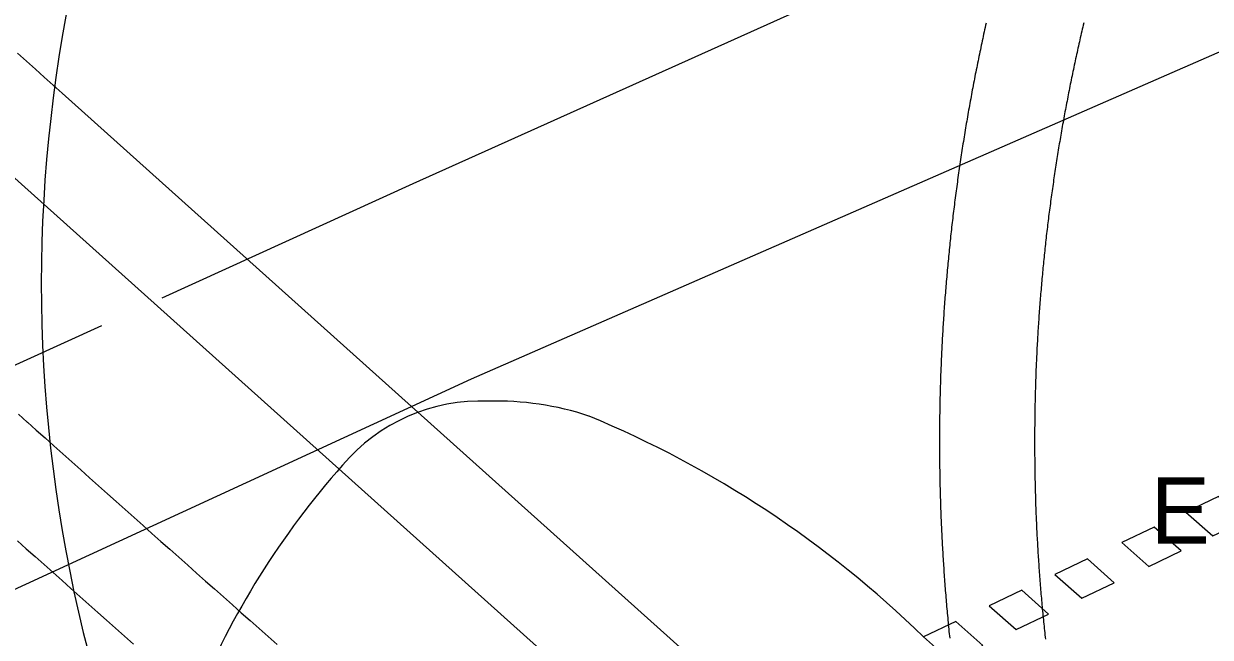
# Model space of a CAD drawing. Extents: x 81617 to 82144, y 454649 to 455150.
# Drawn here: x 81697.46 to 81715.37, y 454732.19 to 454741.45 of the extents above; entities that cross this region are included whole.
import ezdxf

# ---------------------------------------------------------------- set-up
doc = ezdxf.new("R2010")
doc.units = 0
doc.layers.add('B-WE-OG-TOPOGRAFIE-G', color=7, linetype='Continuous')
doc.layers.add('B-WE-VW-MARKERING-G', color=7, linetype='Continuous')

msp = doc.modelspace()

# ---------------------------------------------------------------- linework, layer by layer
at = {"layer": 'B-WE-OG-TOPOGRAFIE-G'}
for points in [[(81711.983, 454741.464), (81711.975, 454741.43), (81711.968, 454741.397), (81711.96, 454741.363), (81711.953, 454741.329), (81711.945, 454741.296), (81711.938, 454741.262), (81711.931, 454741.229), (81711.924, 454741.195), (81711.916, 454741.162), (81711.909, 454741.128), (81711.902, 454741.094), (81711.895, 454741.061), (81711.888, 454741.027), (81711.881, 454740.994), (81711.874, 454740.96), (81711.867, 454740.926), (81711.86, 454740.893), (81711.853, 454740.859), (81711.846, 454740.825), (81711.84, 454740.792), (81711.833, 454740.758), (81711.826, 454740.724), (81711.819, 454740.691), (81711.813, 454740.657), (81711.806, 454740.623), (81711.8, 454740.59), (81711.793, 454740.556), (81711.787, 454740.522), (81711.78, 454740.488), (81711.774, 454740.455), (81711.768, 454740.421), (81711.761, 454740.387), (81711.755, 454740.353), (81711.749, 454740.319), (81711.743, 454740.286), (81711.737, 454740.252), (81711.731, 454740.218), (81711.724, 454740.184), (81711.718, 454740.15), (81711.712, 454740.117), (81711.707, 454740.083), (81711.701, 454740.049), (81711.695, 454740.015), (81711.689, 454739.981), (81711.683, 454739.947), (81711.678, 454739.914), (81711.672, 454739.88), (81711.666, 454739.846), (81711.661, 454739.812), (81711.655, 454739.778), (81711.649, 454739.744), (81711.644, 454739.71), (81711.639, 454739.676), (81711.633, 454739.642), (81711.628, 454739.608), (81711.622, 454739.574), (81711.617, 454739.541), (81711.612, 454739.507), (81711.607, 454739.473), (81711.602, 454739.439), (81711.596, 454739.405), (81711.591, 454739.371), (81711.586, 454739.337), (81711.581, 454739.303), (81711.576, 454739.269), (81711.572, 454739.235), (81711.567, 454739.201), (81711.562, 454739.167), (81711.557, 454739.133), (81711.552, 454739.099), (81711.548, 454739.065), (81711.543, 454739.031), (81711.538, 454738.997), (81711.534, 454738.963), (81711.529, 454738.929), (81711.525, 454738.895), (81711.52, 454738.861), (81711.516, 454738.826), (81711.511, 454738.792), (81711.507, 454738.758), (81711.503, 454738.724), (81711.498, 454738.69), (81711.494, 454738.656), (81711.49, 454738.622), (81711.486, 454738.588), (81711.482, 454738.554), (81711.478, 454738.52), (81711.474, 454738.486), (81711.47, 454738.451), (81711.466, 454738.417), (81711.462, 454738.383), (81711.458, 454738.349), (81711.454, 454738.315), (81711.45, 454738.281), (81711.447, 454738.247), (81711.443, 454738.212), (81711.439, 454738.178), (81711.436, 454738.144), (81711.432, 454738.11), (81711.429, 454738.076), (81711.425, 454738.042), (81711.422, 454738.008), (81711.418, 454737.973), (81711.415, 454737.939), (81711.412, 454737.905), (81711.408, 454737.871), (81711.405, 454737.837), (81711.402, 454737.802), (81711.399, 454737.768), (81711.396, 454737.734), (81711.393, 454737.7), (81711.389, 454737.666), (81711.387, 454737.631), (81711.384, 454737.597), (81711.381, 454737.563), (81711.378, 454737.529), (81711.375, 454737.494), (81711.372, 454737.46), (81711.369, 454737.426), (81711.367, 454737.392), (81711.364, 454737.357), (81711.361, 454737.323), (81711.359, 454737.289), (81711.356, 454737.255), (81711.354, 454737.22), (81711.351, 454737.186), (81711.349, 454737.152), (81711.346, 454737.118), (81711.344, 454737.083), (81711.342, 454737.049), (81711.34, 454737.015), (81711.337, 454736.981), (81711.335, 454736.946), (81711.333, 454736.912), (81711.331, 454736.878), (81711.329, 454736.843), (81711.327, 454736.809), (81711.325, 454736.775), (81711.323, 454736.741), (81711.321, 454736.706), (81711.319, 454736.672), (81711.317, 454736.638), (81711.316, 454736.603), (81711.314, 454736.569), (81711.312, 454736.535), (81711.311, 454736.5), (81711.309, 454736.466), (81711.307, 454736.432), (81711.306, 454736.398), (81711.304, 454736.363), (81711.303, 454736.329), (81711.302, 454736.295), (81711.3, 454736.26), (81711.299, 454736.226), (81711.298, 454736.192), (81711.296, 454736.157), (81711.295, 454736.123), (81711.294, 454736.089), (81711.293, 454736.054), (81711.292, 454736.02), (81711.291, 454735.986), (81711.29, 454735.951), (81711.289, 454735.917), (81711.288, 454735.883), (81711.287, 454735.848), (81711.286, 454735.814), (81711.286, 454735.78), (81711.285, 454735.745), (81711.284, 454735.711), (81711.283, 454735.677), (81711.283, 454735.642), (81711.282, 454735.608), (81711.282, 454735.574), (81711.281, 454735.539), (81711.281, 454735.505), (81711.28, 454735.471), (81711.28, 454735.436), (81711.28, 454735.402), (81711.279, 454735.367), (81711.279, 454735.333), (81711.279, 454735.299), (81711.279, 454735.264), (81711.279, 454735.23), (81711.279, 454735.196), (81711.278, 454735.161), (81711.278, 454735.127), (81711.279, 454735.093), (81711.279, 454735.058), (81711.279, 454735.024), (81711.279, 454734.99), (81711.279, 454734.955), (81711.279, 454734.921), (81711.28, 454734.887), (81711.28, 454734.852), (81711.28, 454734.818), (81711.281, 454734.784), (81711.281, 454734.749), (81711.282, 454734.715), (81711.282, 454734.681), (81711.283, 454734.646), (81711.283, 454734.612), (81711.284, 454734.578), (81711.285, 454734.543), (81711.285, 454734.509), (81711.286, 454734.475), (81711.287, 454734.44), (81711.288, 454734.406), (81711.289, 454734.372), (81711.29, 454734.337), (81711.291, 454734.303), (81711.292, 454734.269), (81711.293, 454734.234), (81711.294, 454734.2), (81711.295, 454734.166), (81711.296, 454734.131), (81711.298, 454734.097), (81711.299, 454734.063), (81711.3, 454734.028), (81711.301, 454733.994), (81711.303, 454733.96), (81711.304, 454733.925), (81711.306, 454733.891), (81711.307, 454733.857), (81711.309, 454733.822), (81711.31, 454733.788), (81711.312, 454733.754), (81711.314, 454733.719), (81711.316, 454733.685), (81711.317, 454733.651), (81711.319, 454733.616), (81711.321, 454733.582), (81711.323, 454733.548), (81711.325, 454733.514), (81711.327, 454733.479), (81711.329, 454733.445), (81711.331, 454733.411), (81711.333, 454733.376), (81711.335, 454733.342), (81711.337, 454733.308), (81711.339, 454733.274), (81711.342, 454733.239), (81711.344, 454733.205), (81711.346, 454733.171), (81711.349, 454733.137), (81711.351, 454733.102), (81711.354, 454733.068), (81711.356, 454733.034), (81711.359, 454732.999), (81711.361, 454732.965), (81711.364, 454732.931), (81711.366, 454732.897), (81711.369, 454732.863), (81711.372, 454732.828), (81711.375, 454732.794), (81711.378, 454732.76), (81711.38, 454732.726), (81711.383, 454732.691), (81711.386, 454732.657), (81711.389, 454732.623), (81711.392, 454732.589), (81711.395, 454732.555), (81711.398, 454732.52), (81711.402, 454732.486), (81711.405, 454732.452), (81711.408, 454732.418), (81711.411, 454732.384), (81711.415, 454732.349), (81711.418, 454732.315), (81711.421, 454732.281), (81711.425, 454732.247), (81711.428, 454732.213), (81711.432, 454732.178)], [(81713.456, 454741.466), (81713.449, 454741.434), (81713.441, 454741.402), (81713.434, 454741.37), (81713.426, 454741.339), (81713.419, 454741.307), (81713.412, 454741.275), (81713.404, 454741.243), (81713.397, 454741.211), (81713.39, 454741.18), (81713.383, 454741.148), (81713.375, 454741.116), (81713.368, 454741.084), (81713.361, 454741.052), (81713.354, 454741.02), (81713.347, 454740.988), (81713.34, 454740.957), (81713.333, 454740.925), (81713.326, 454740.893), (81713.319, 454740.861), (81713.313, 454740.829), (81713.306, 454740.797), (81713.299, 454740.765), (81713.292, 454740.733), (81713.286, 454740.701), (81713.279, 454740.669), (81713.272, 454740.637), (81713.266, 454740.605), (81713.259, 454740.573), (81713.253, 454740.541), (81713.246, 454740.509), (81713.24, 454740.477), (81713.234, 454740.445), (81713.227, 454740.413), (81713.221, 454740.381), (81713.215, 454740.349), (81713.209, 454740.317), (81713.203, 454740.285), (81713.196, 454740.253), (81713.19, 454740.221), (81713.184, 454740.189), (81713.178, 454740.157), (81713.172, 454740.125), (81713.166, 454740.093), (81713.16, 454740.061), (81713.155, 454740.029), (81713.149, 454739.997), (81713.143, 454739.964), (81713.137, 454739.932), (81713.131, 454739.9), (81713.126, 454739.868), (81713.12, 454739.836), (81713.115, 454739.804), (81713.109, 454739.772), (81713.103, 454739.739), (81713.098, 454739.707), (81713.093, 454739.675), (81713.087, 454739.643), (81713.082, 454739.611), (81713.076, 454739.579), (81713.071, 454739.546), (81713.066, 454739.514), (81713.061, 454739.482), (81713.056, 454739.45), (81713.05, 454739.418), (81713.045, 454739.385), (81713.04, 454739.353), (81713.035, 454739.321), (81713.03, 454739.289), (81713.025, 454739.256), (81713.02, 454739.224), (81713.016, 454739.192), (81713.011, 454739.159), (81713.006, 454739.127), (81713.001, 454739.095), (81712.997, 454739.063), (81712.992, 454739.03), (81712.987, 454738.998), (81712.983, 454738.966), (81712.978, 454738.933), (81712.974, 454738.901), (81712.969, 454738.869), (81712.965, 454738.836), (81712.96, 454738.804), (81712.956, 454738.772), (81712.952, 454738.739), (81712.947, 454738.707), (81712.943, 454738.675), (81712.939, 454738.642), (81712.935, 454738.61), (81712.931, 454738.578), (81712.926, 454738.545), (81712.922, 454738.513), (81712.918, 454738.481), (81712.914, 454738.448), (81712.911, 454738.416), (81712.907, 454738.383), (81712.903, 454738.351), (81712.899, 454738.319), (81712.895, 454738.286), (81712.891, 454738.254), (81712.888, 454738.221), (81712.884, 454738.189), (81712.88, 454738.156), (81712.877, 454738.124), (81712.873, 454738.092), (81712.87, 454738.059), (81712.866, 454738.027), (81712.863, 454737.994), (81712.859, 454737.962), (81712.856, 454737.929), (81712.853, 454737.897), (81712.85, 454737.864), (81712.846, 454737.832), (81712.843, 454737.799), (81712.84, 454737.767), (81712.837, 454737.734), (81712.834, 454737.702), (81712.831, 454737.669), (81712.828, 454737.637), (81712.825, 454737.604), (81712.822, 454737.572), (81712.819, 454737.539), (81712.816, 454737.507), (81712.813, 454737.474), (81712.811, 454737.442), (81712.808, 454737.409), (81712.805, 454737.377), (81712.802, 454737.344), (81712.8, 454737.312), (81712.797, 454737.279), (81712.795, 454737.247), (81712.792, 454737.214), (81712.79, 454737.182), (81712.787, 454737.149), (81712.785, 454737.117), (81712.783, 454737.084), (81712.78, 454737.052), (81712.778, 454737.019), (81712.776, 454736.986), (81712.774, 454736.954), (81712.772, 454736.921), (81712.769, 454736.889), (81712.767, 454736.856), (81712.765, 454736.824), (81712.763, 454736.791), (81712.761, 454736.758), (81712.759, 454736.726), (81712.758, 454736.693), (81712.756, 454736.661), (81712.754, 454736.628), (81712.752, 454736.596), (81712.75, 454736.563), (81712.749, 454736.53), (81712.747, 454736.498), (81712.746, 454736.465), (81712.744, 454736.433), (81712.742, 454736.4), (81712.741, 454736.367), (81712.74, 454736.335), (81712.738, 454736.302), (81712.737, 454736.27), (81712.735, 454736.237), (81712.734, 454736.204), (81712.733, 454736.172), (81712.732, 454736.139), (81712.731, 454736.107), (81712.729, 454736.074), (81712.728, 454736.041), (81712.727, 454736.009), (81712.726, 454735.976), (81712.725, 454735.944), (81712.724, 454735.911), (81712.723, 454735.878), (81712.723, 454735.846), (81712.722, 454735.813), (81712.721, 454735.78), (81712.72, 454735.748), (81712.719, 454735.715), (81712.719, 454735.683), (81712.718, 454735.65), (81712.718, 454735.617), (81712.717, 454735.585), (81712.717, 454735.552), (81712.716, 454735.519), (81712.716, 454735.487), (81712.715, 454735.454), (81712.715, 454735.422), (81712.715, 454735.389), (81712.714, 454735.356), (81712.714, 454735.324), (81712.714, 454735.291), (81712.714, 454735.258), (81712.714, 454735.226), (81712.714, 454735.193), (81712.713, 454735.16), (81712.713, 454735.128), (81712.714, 454735.095), (81712.714, 454735.063), (81712.714, 454735.03), (81712.714, 454734.997), (81712.714, 454734.965), (81712.714, 454734.932), (81712.715, 454734.899), (81712.715, 454734.867), (81712.715, 454734.834), (81712.716, 454734.802), (81712.716, 454734.769), (81712.717, 454734.736), (81712.717, 454734.704), (81712.718, 454734.671), (81712.718, 454734.638), (81712.719, 454734.606), (81712.719, 454734.573), (81712.72, 454734.541), (81712.721, 454734.508), (81712.722, 454734.475), (81712.722, 454734.443), (81712.723, 454734.41), (81712.724, 454734.377), (81712.725, 454734.345), (81712.726, 454734.312), (81712.727, 454734.28), (81712.728, 454734.247), (81712.729, 454734.214), (81712.73, 454734.182), (81712.732, 454734.149), (81712.733, 454734.117), (81712.734, 454734.084), (81712.735, 454734.051), (81712.737, 454734.019), (81712.738, 454733.986), (81712.739, 454733.954), (81712.741, 454733.921), (81712.742, 454733.888), (81712.744, 454733.856), (81712.745, 454733.823), (81712.747, 454733.791), (81712.749, 454733.758), (81712.75, 454733.725), (81712.752, 454733.693), (81712.754, 454733.66), (81712.756, 454733.628), (81712.757, 454733.595), (81712.759, 454733.562), (81712.761, 454733.53), (81712.763, 454733.497), (81712.765, 454733.465), (81712.767, 454733.432), (81712.769, 454733.4), (81712.771, 454733.367), (81712.773, 454733.334), (81712.776, 454733.302), (81712.778, 454733.269), (81712.78, 454733.237), (81712.782, 454733.204), (81712.785, 454733.172), (81712.787, 454733.139), (81712.79, 454733.107), (81712.792, 454733.074), (81712.795, 454733.042), (81712.797, 454733.009), (81712.8, 454732.976), (81712.802, 454732.944), (81712.805, 454732.911), (81712.808, 454732.879), (81712.81, 454732.846), (81712.813, 454732.814), (81712.816, 454732.781), (81712.819, 454732.749), (81712.822, 454732.716), (81712.825, 454732.684), (81712.827, 454732.651), (81712.83, 454732.619), (81712.834, 454732.586), (81712.837, 454732.554), (81712.84, 454732.521), (81712.843, 454732.489), (81712.846, 454732.456), (81712.849, 454732.424), (81712.853, 454732.392), (81712.856, 454732.359), (81712.859, 454732.327), (81712.863, 454732.294), (81712.866, 454732.262), (81712.87, 454732.229), (81712.873, 454732.197), (81712.877, 454732.164)], [(81733.293, 454708.784), (81733.175, 454708.889), (81733.058, 454708.994), (81732.94, 454709.1), (81732.94, 454709.1), (81698.035, 454740.405), (81698.035, 454740.405), (81697.901, 454740.525), (81697.766, 454740.646), (81697.632, 454740.766), (81697.498, 454740.887), (81697.364, 454741.007)], [(81733.393, 454706.767), (81733.276, 454706.872), (81733.158, 454706.977), (81733.04, 454707.083), (81732.923, 454707.188), (81732.805, 454707.294), (81732.688, 454707.399), (81732.57, 454707.504), (81732.452, 454707.61), (81732.335, 454707.715), (81732.217, 454707.821), (81732.1, 454707.926), (81731.982, 454708.032), (81731.982, 454708.032), (81697.077, 454739.337)], [(81697.376, 454735.562), (81697.51, 454735.441), (81697.511, 454735.441), (81697.645, 454735.321), (81697.779, 454735.201), (81697.913, 454735.081), (81698.048, 454734.961), (81698.182, 454734.84), (81698.316, 454734.72), (81698.451, 454734.6), (81698.585, 454734.48), (81698.72, 454734.36), (81698.854, 454734.24), (81698.989, 454734.12), (81699.123, 454734), (81699.258, 454733.88), (81699.392, 454733.761), (81699.527, 454733.641), (81699.662, 454733.521), (81699.796, 454733.401), (81699.931, 454733.281), (81700.066, 454733.162), (81700.201, 454733.042), (81700.335, 454732.922), (81700.47, 454732.803), (81700.605, 454732.683), (81700.74, 454732.564), (81700.875, 454732.444), (81701.01, 454732.325), (81701.145, 454732.205), (81701.28, 454732.086)], [(81697.36, 454733.65), (81697.495, 454733.53), (81697.63, 454733.41), (81697.764, 454733.289), (81697.899, 454733.169), (81698.034, 454733.049), (81698.169, 454732.929), (81698.303, 454732.809), (81698.438, 454732.689), (81698.573, 454732.569), (81698.708, 454732.449), (81698.843, 454732.329), (81698.978, 454732.209), (81699.113, 454732.089)]]:
    msp.add_lwpolyline(points, dxfattribs=at)
at = {"layer": 'B-WE-VW-MARKERING-G'}
for points in [[(81699.546, 454737.316), (81703.335, 454739.043), (81714.567, 454744.092)], [(81689.688, 454729.154), (81696.008, 454732.316), (81704.216, 454736.092), (81716.472, 454741.453)], [(81688.131, 454731.94), (81696.375, 454735.872), (81698.635, 454736.901)]]:
    msp.add_lwpolyline(points, dxfattribs=at)
for points in [[(81715.895, 454733.957), (81715.489, 454734.317), (81714.998, 454734.083), (81715.405, 454733.723)], [(81714.926, 454733.496), (81714.52, 454733.856), (81714.029, 454733.622), (81714.436, 454733.262)], [(81713.916, 454733.015), (81713.51, 454733.375), (81713.019, 454733.142), (81713.426, 454732.781)], [(81712.926, 454732.543), (81712.519, 454732.904), (81712.028, 454732.67), (81712.435, 454732.31)], [(81711.934, 454732.071), (81711.527, 454732.432), (81711.037, 454732.198), (81711.443, 454731.838)]]:
    msp.add_lwpolyline(points, close=True, dxfattribs=at)
for centre, radius, start, end in [((81719.891, 454737.529), 22.169, 149.9749, 201.9261), ((81704.355, 454733.03), 2.729, 87.6397, 139.8412), ((81704.596, 454731.365), 4.393, 71.5255, 91.6745), ((81699.806, 454720.683), 16.085, 45.716, 67.3954), ((81711.569, 454726.522), 12.444, 138.3584, 157.6665)]:
    msp.add_arc(centre, radius, start, end, dxfattribs=at)

# ---------------------------------------------------------------- texts
at = {"layer": 'B-WE-OG-TOPOGRAFIE-G'}
msp.add_text('E', height=1, dxfattribs=at).set_placement((81714.468, 454733.608))

doc.saveas('drawing.dxf')
